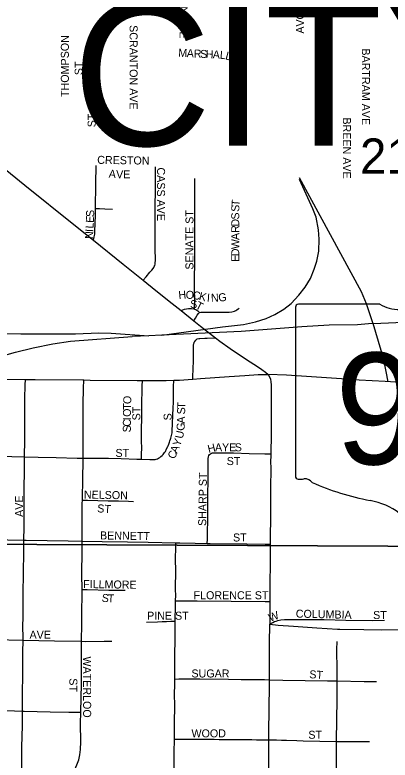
# Model space of a CAD drawing. Extents: x -97 to 34, y -21 to 22.
# Drawn here: x 4.656 to 5.1, y 19.223 to 20.104 of the extents above; entities that cross this region are included whole.
import ezdxf

# ---------------------------------------------------------------- set-up
doc = ezdxf.new("R2010")
doc.units = 0
for name, color, linetype in [('GM_X_City_Street', 7, 'Continuous'), ('GM_X_City_Street_Text', 7, 'Continuous'), ('GM_X_Rail_Line', 7, 'Continuous'), ('GM_X_Section', 7, 'Continuous'), ('GM_X_Section_Text', 7, 'Continuous'), ('GM_X_State_Location', 7, 'Continuous'), ('GM_X_State_Route', 7, 'Continuous'), ('GM_X_State_Shield', 7, 'Continuous'), ('GM_X_Township_Text', 7, 'Continuous')]:
    doc.layers.add(name, color=color, linetype=linetype)

msp = doc.modelspace()

# ---------------------------------------------------------------- linework, layer by layer
at = {"layer": 'GM_X_City_Street'}
for points in [[(4.75175, 19.87547), (4.75216, 19.90473), (4.75252, 19.92642)], [(4.80785, 19.79053), (4.81156, 19.79472), (4.81599, 19.79992), (4.81816, 19.80261), (4.81975, 19.80461), (4.82047, 19.8056), (4.82109, 19.80663), (4.82166, 19.80797), (4.82202, 19.80946), (4.82228, 19.81142), (4.82242, 19.81344), (4.82252, 19.81653), (4.82233, 19.8258), (4.82236, 19.84434), (4.82224, 19.8598), (4.82224, 19.87834), (4.82252, 19.89688), (4.82249, 19.90923), (4.82254, 19.9185), (4.82249, 19.92466)], [(4.86888, 19.75652), (4.86895, 19.75977), (4.86901, 19.76275), (4.86873, 19.7846), (4.86897, 19.81885), (4.86921, 19.91092)], [(4.74904, 19.83794), (4.75013, 19.84192), (4.7507, 19.84511), (4.75097, 19.848), (4.75164, 19.86754), (4.75175, 19.87547)], [(4.75175, 19.87547), (4.75642, 19.87528), (4.76256, 19.87503), (4.77189, 19.87466)], [(4.85305, 19.75462), (4.85708, 19.75622), (4.85912, 19.75672), (4.86179, 19.75704), (4.8654, 19.75717), (4.86794, 19.75685), (4.86888, 19.75652)], [(4.8681, 19.74272), (4.86991, 19.74575), (4.872, 19.74924), (4.87333, 19.75114), (4.87466, 19.75241)], [(4.86888, 19.75652), (4.87029, 19.75603), (4.87257, 19.75451), (4.87466, 19.75241)], [(4.87466, 19.75241), (4.87625, 19.75273), (4.87879, 19.75285), (4.88152, 19.75279), (4.88702, 19.75282), (4.89974, 19.75267), (4.90633, 19.75267), (4.90971, 19.75287), (4.91282, 19.75331), (4.91454, 19.75372), (4.916, 19.75413), (4.91774, 19.75487), (4.91904, 19.75559), (4.92047, 19.75658), (4.92155, 19.75763)], [(4.86665, 19.67348), (4.86676, 19.67633), (4.86747, 19.69511), (4.86757, 19.71082), (4.86755, 19.71237), (4.86771, 19.71394), (4.86797, 19.71557), (4.86823, 19.71661), (4.86849, 19.71745), (4.86897, 19.71819)], [(4.86897, 19.71819), (4.87023, 19.71981), (4.87112, 19.7206), (4.8721, 19.72112), (4.87374, 19.72149), (4.87514, 19.72166), (4.88101, 19.72198), (4.88383, 19.72211), (4.89344, 19.72257)], [(4.6676, 19.58171), (4.6676, 19.58556), (4.66773, 19.59798), (4.66796, 19.62903), (4.66802, 19.65076), (4.66851, 19.66628), (4.66872, 19.67329)], [(4.73686, 19.58003), (4.73682, 19.60364), (4.73687, 19.64398), (4.73738, 19.6626), (4.73764, 19.6726)], [(4.82761, 19.58085), (4.82905, 19.58195), (4.83045, 19.58314), (4.83154, 19.58433), (4.83247, 19.58544), (4.83335, 19.58671), (4.83424, 19.5881), (4.83575, 19.59107), (4.83701, 19.59384), (4.83744, 19.59485), (4.83818, 19.59657), (4.83869, 19.5978), (4.8392, 19.59908), (4.8397, 19.60041), (4.84042, 19.6024), (4.84084, 19.60384), (4.84133, 19.6054), (4.84172, 19.60697), (4.84202, 19.60842), (4.84228, 19.61013), (4.84244, 19.61198), (4.84335, 19.63971), (4.84373, 19.64587), (4.84381, 19.66132), (4.84391, 19.66441), (4.84419, 19.67223)], [(4.80607, 19.57877), (4.80618, 19.58543), (4.80628, 19.59168), (4.80617, 19.60093), (4.80623, 19.6409), (4.80693, 19.66543), (4.80711, 19.67186)], [(4.88568, 19.58341), (4.88669, 19.58457), (4.88777, 19.58534), (4.889, 19.58589), (4.89025, 19.58628), (4.89141, 19.58643), (4.89296, 19.58641), (4.89497, 19.58639), (4.8993, 19.58636), (4.91499, 19.58623), (4.93354, 19.5858), (4.95209, 19.58535), (4.95907, 19.58518)], [(4.59809, 19.58323), (4.60332, 19.58314), (4.61567, 19.58295), (4.63108, 19.58269), (4.65267, 19.58195), (4.6676, 19.58171)], [(4.66685, 19.48317), (4.66695, 19.49861), (4.66731, 19.54209), (4.6676, 19.56693), (4.6676, 19.58171)], [(4.6676, 19.58171), (4.68365, 19.58123), (4.7052, 19.5807), (4.7298, 19.58), (4.73686, 19.58003)], [(4.73603, 19.53043), (4.73644, 19.55718), (4.73687, 19.57574), (4.73686, 19.58003)], [(4.73686, 19.58003), (4.74833, 19.58008), (4.76679, 19.57991), (4.78209, 19.57965), (4.80068, 19.57893), (4.80607, 19.57877)], [(4.80607, 19.57877), (4.81597, 19.57847), (4.81902, 19.57846), (4.82048, 19.5785), (4.82206, 19.57863), (4.82357, 19.5789), (4.82498, 19.57939), (4.82633, 19.58003), (4.82761, 19.58085)], [(4.88386, 19.47935), (4.88395, 19.48447), (4.88446, 19.5149), (4.8845, 19.51807), (4.88455, 19.52113), (4.88451, 19.5303), (4.88461, 19.53317), (4.88461, 19.53603), (4.88469, 19.53905), (4.885, 19.55155), (4.88497, 19.57621), (4.88497, 19.57753), (4.88498, 19.57962), (4.88521, 19.58155), (4.88568, 19.58341)], [(4.73581, 19.48202), (4.73592, 19.5263), (4.73603, 19.53043)], [(4.73603, 19.53043), (4.74212, 19.53029), (4.76658, 19.52979), (4.77863, 19.52945), (4.79047, 19.52923), (4.79664, 19.52883)], [(4.59728, 19.48431), (4.61686, 19.4842), (4.63233, 19.48391), (4.64781, 19.48371), (4.66685, 19.48317)], [(4.6658, 19.36465), (4.66581, 19.37148), (4.66573, 19.37758), (4.6659, 19.39618), (4.66595, 19.40548), (4.6659, 19.4179), (4.66635, 19.44583), (4.66677, 19.46756), (4.66685, 19.48317)], [(4.66685, 19.48317), (4.66949, 19.48309), (4.71912, 19.48227), (4.73581, 19.48202)], [(4.73567, 19.42469), (4.73553, 19.44258), (4.73578, 19.4705), (4.73581, 19.48202)], [(4.73581, 19.48202), (4.75939, 19.48167), (4.78954, 19.48098), (4.81404, 19.48056), (4.8466, 19.48006)], [(4.84643, 19.41134), (4.84655, 19.41812), (4.84634, 19.42433), (4.84637, 19.43367), (4.84658, 19.43883), (4.84648, 19.44299), (4.84645, 19.46471), (4.84652, 19.47093), (4.8466, 19.48006)], [(4.8466, 19.48006), (4.8512, 19.47999), (4.86952, 19.47961), (4.88386, 19.47935)], [(4.88386, 19.47935), (4.88741, 19.47928), (4.93068, 19.47885), (4.95234, 19.47851), (4.95837, 19.47841)], [(4.73507, 19.36351), (4.73523, 19.3843), (4.73536, 19.39647), (4.73569, 19.4209), (4.73567, 19.42469)], [(4.73567, 19.42469), (4.74178, 19.42459), (4.76736, 19.42416), (4.78655, 19.42401)], [(4.84601, 19.38744), (4.84605, 19.39348), (4.84619, 19.3998), (4.8464, 19.40879), (4.84643, 19.41134)], [(4.84643, 19.41134), (4.85087, 19.41145), (4.85994, 19.41149), (4.87178, 19.41145), (4.95226, 19.41074), (4.95803, 19.41068)], [(4.8121, 19.38618), (4.8249, 19.38659), (4.83052, 19.38682), (4.83578, 19.38703), (4.84089, 19.38723), (4.84601, 19.38744)], [(4.84559, 19.31882), (4.84563, 19.32228), (4.84553, 19.33472), (4.84541, 19.34093), (4.84556, 19.34712), (4.84587, 19.36572), (4.84603, 19.37504), (4.84597, 19.38116), (4.84601, 19.38643), (4.84601, 19.38744)], [(4.95737, 19.318), (4.95737, 19.3238), (4.95762, 19.33626), (4.9575, 19.34249), (4.95757, 19.34866), (4.95762, 19.35801), (4.95772, 19.3611), (4.95786, 19.38371)], [(4.95786, 19.38371), (4.96145, 19.38574), (4.96351, 19.38674), (4.96555, 19.38739), (4.96753, 19.38803), (4.97088, 19.38873), (4.97542, 19.3891), (4.99161, 19.38929), (5.01598, 19.38939), (5.02207, 19.38928), (5.04801, 19.3884), (5.07954, 19.38824), (5.09364, 19.38844)], [(4.59598, 19.36586), (4.60664, 19.36575), (4.63147, 19.36554), (4.66562, 19.36466), (4.6658, 19.36465)], [(4.66497, 19.28102), (4.66504, 19.28569), (4.66509, 19.28978), (4.66516, 19.2945), (4.66521, 19.29833), (4.66529, 19.30363), (4.66535, 19.30957), (4.66541, 19.31602), (4.66545, 19.32107), (4.66549, 19.32503), (4.66553, 19.32912), (4.66557, 19.33307), (4.66561, 19.3378), (4.66565, 19.34266), (4.66569, 19.34661), (4.66575, 19.35297), (4.6658, 19.36222), (4.6658, 19.36465)], [(4.6658, 19.36465), (4.70287, 19.36401), (4.73507, 19.36351)], [(4.73507, 19.36351), (4.74006, 19.36343), (4.76165, 19.36375), (4.77095, 19.36365)], [(4.73416, 19.27957), (4.735, 19.31317), (4.73499, 19.35341), (4.73507, 19.36351)], [(5.0375, 19.31656), (5.03749, 19.32919), (5.03738, 19.35387), (5.0376, 19.36316)], [(4.84506, 19.24776), (4.8452, 19.25389), (4.84517, 19.26636), (4.84547, 19.28813), (4.84516, 19.30053), (4.84551, 19.31293), (4.84559, 19.31882)], [(4.84559, 19.31882), (4.85024, 19.31894), (4.85955, 19.31919), (4.87507, 19.31894), (4.90917, 19.31862), (4.92417, 19.31847), (4.95167, 19.31814), (4.95737, 19.318)], [(4.95686, 19.24688), (4.95688, 19.25243), (4.95712, 19.2866), (4.95745, 19.30827), (4.9574, 19.31449), (4.95737, 19.318)], [(4.95737, 19.318), (4.97339, 19.31761), (5.02619, 19.31673), (5.0375, 19.31656)], [(5.03686, 19.24518), (5.03687, 19.2459), (5.03756, 19.29519), (5.0375, 19.31656)], [(5.0375, 19.31656), (5.06953, 19.31609), (5.08406, 19.31584)], [(4.59643, 19.28289), (4.63586, 19.28191), (4.66497, 19.28102)], [(4.6685, 19.13409), (4.66685, 19.13448), (4.66608, 19.13479), (4.66522, 19.1354), (4.66442, 19.13657), (4.66406, 19.13819), (4.66391, 19.13982), (4.66386, 19.14266), (4.66389, 19.15508), (4.66381, 19.1581), (4.66384, 19.16112), (4.66375, 19.1672), (4.66384, 19.17647), (4.66417, 19.19819), (4.66448, 19.21991), (4.66448, 19.23853), (4.66504, 19.26334), (4.66513, 19.27265), (4.66497, 19.28102)], [(4.66497, 19.28102), (4.66696, 19.28095), (4.69807, 19.28008), (4.71986, 19.27966), (4.72479, 19.27969), (4.73416, 19.27957)], [(4.6685, 19.13409), (4.67125, 19.13545), (4.67382, 19.13713), (4.67865, 19.14095), (4.68309, 19.14521), (4.68927, 19.15208), (4.6968, 19.16186), (4.70384, 19.17197), (4.71204, 19.18501), (4.72135, 19.201), (4.72711, 19.2119), (4.72967, 19.2175), (4.73166, 19.22332), (4.73305, 19.22932), (4.73387, 19.23543), (4.73423, 19.24466), (4.73398, 19.26622), (4.73416, 19.27957)], [(4.84457, 19.1783), (4.84487, 19.20417), (4.84469, 19.23216), (4.84506, 19.24776)], [(4.84506, 19.24776), (4.84656, 19.24776), (4.84899, 19.24775), (4.85269, 19.24775), (4.8573, 19.24775), (4.86081, 19.24775), (4.86503, 19.24774), (4.87049, 19.24773), (4.8731, 19.24772), (4.87847, 19.24769), (4.88116, 19.24767), (4.88849, 19.24762), (4.89186, 19.24756), (4.89806, 19.24754), (4.91344, 19.24745), (4.91943, 19.24744), (4.92511, 19.24748), (4.92803, 19.24745), (4.93663, 19.24723), (4.94228, 19.24713), (4.951, 19.247), (4.95686, 19.24688)], [(4.95659, 19.17674), (4.9566, 19.17869), (4.95657, 19.19079), (4.9568, 19.197), (4.95673, 19.1998), (4.95684, 19.22765), (4.95686, 19.24688)], [(4.95686, 19.24688), (4.96275, 19.2468), (4.96564, 19.24679), (4.97164, 19.24657), (4.97774, 19.24645), (4.99, 19.24611), (4.99747, 19.24596), (5.03686, 19.24518)], [(5.03616, 19.17586), (5.03632, 19.19676), (5.03674, 19.22449), (5.03686, 19.24518)], [(5.03686, 19.24518), (5.04217, 19.24505), (5.06351, 19.24485), (5.07581, 19.24507)]]:
    msp.add_lwpolyline(points, dxfattribs=at)
at = {"layer": 'GM_X_Rail_Line'}
for points in [[(5.07985, 19.74006), (5.07224, 19.76264), (5.06653, 19.77664), (4.993, 19.9115)], [(4.82995, 19.72561), (4.90186, 19.73546), (4.9267, 19.73839), (4.94107, 19.74143), (4.95339, 19.74544), (4.96376, 19.75003), (4.97432, 19.75649), (4.98312, 19.76314), (4.99232, 19.77272), (4.99965, 19.7823), (5.00591, 19.79277), (5.01051, 19.80353), (5.01354, 19.81291), (5.01579, 19.82484), (5.01628, 19.83932), (5.0154, 19.85008), (5.01266, 19.86504), (5.00875, 19.87501), (4.99299, 19.90954)], [(3.55146, 19.84605), (3.99437, 19.79548), (4.36844, 19.75302), (4.56422, 19.73118), (4.58914, 19.72923), (4.61241, 19.7276), (4.66323, 19.72698), (4.72805, 19.72735), (4.75546, 19.72823), (4.77023, 19.72786), (4.81467, 19.72488)], [(5.07455, 19.73891), (5.0615, 19.738), (5.02805, 19.73723), (4.99596, 19.73538), (4.9239, 19.73003), (4.82995, 19.72561)], [(5.08011, 19.73929), (5.07455, 19.73891)], [(5.08011, 19.73929), (5.07985, 19.74006)], [(5.08011, 19.73929), (5.12506, 19.74133)], [(5.09818, 19.67056), (5.09279, 19.69666), (5.08011, 19.73929)], [(4.82995, 19.72561), (4.81467, 19.72488)], [(4.63887, 19.70027), (4.65686, 19.70533), (4.67777, 19.71068), (4.7012, 19.71525), (4.72192, 19.71846), (4.79498, 19.72393)], [(4.81467, 19.72488), (4.79498, 19.72393)]]:
    msp.add_lwpolyline(points, dxfattribs=at)
at = {"layer": 'GM_X_Section'}
for points in [[(4.59907, 20.48403), (5.59805, 20.47457), (5.59615, 19.47364), (4.59865, 19.47855)], [(4.59865, 19.47855), (5.59615, 19.47364), (5.59082, 18.47236), (4.59557, 18.47233)]]:
    msp.add_lwpolyline(points, close=True, dxfattribs=at)
at = {"layer": 'GM_X_State_Route'}
for points in [[(4.60122, 19.95654), (4.62915, 19.93424), (4.66788, 19.90309), (4.72606, 19.85642), (4.74904, 19.83794), (4.78415, 19.80968), (4.80785, 19.79053), (4.82281, 19.77844), (4.84237, 19.76308), (4.85305, 19.75462), (4.8681, 19.74272), (4.87591, 19.73633), (4.88286, 19.73083), (4.89017, 19.72505), (4.89344, 19.72257), (4.89873, 19.71857), (4.91115, 19.70981), (4.93154, 19.69606), (4.94212, 19.68913), (4.94841, 19.68504), (4.95266, 19.68192), (4.95603, 19.67899)], [(4.54599, 19.67245), (4.55588, 19.67222), (4.5776, 19.673), (4.58596, 19.67309), (4.59001, 19.67314), (4.59856, 19.67326), (4.61174, 19.67342), (4.66872, 19.67329), (4.68006, 19.67326), (4.73665, 19.67261)], [(4.73665, 19.67261), (4.73764, 19.6726), (4.74527, 19.67251), (4.80104, 19.67188), (4.80711, 19.67186), (4.816, 19.67183), (4.83538, 19.67186), (4.84419, 19.67223), (4.85093, 19.67252), (4.86128, 19.67302), (4.86665, 19.67348), (4.87573, 19.67426), (4.9098, 19.67661), (4.92839, 19.67807), (4.94399, 19.67922), (4.95603, 19.67899)], [(4.95603, 19.67899), (4.95749, 19.67631), (4.95856, 19.67358), (4.95914, 19.67051), (4.95941, 19.66666), (4.9594, 19.65975), (4.95939, 19.64811), (4.95932, 19.60786), (4.95908, 19.58615), (4.95907, 19.58518), (4.9589, 19.57373), (4.95895, 19.57071), (4.95893, 19.5627), (4.95891, 19.55033), (4.9589, 19.54131), (4.95888, 19.53368), (4.95866, 19.51822), (4.95837, 19.47841), (4.95827, 19.46541), (4.95808, 19.42209), (4.95803, 19.41068), (4.95801, 19.40654), (4.95786, 19.38371)], [(5.05471, 19.67312), (4.97754, 19.67823), (4.95603, 19.67899)], [(5.1646, 19.66835), (5.16362, 19.66839), (5.1593, 19.66856), (5.15293, 19.66855), (5.14899, 19.66833), (5.14545, 19.668), (5.1377, 19.66842), (5.1188, 19.66943), (5.11296, 19.66961), (5.09448, 19.6706), (5.06369, 19.67252), (5.05471, 19.67312)], [(4.95786, 19.38371), (4.9678, 19.38269), (4.9858, 19.38134), (5.01352, 19.37928), (5.03817, 19.37801), (5.04062, 19.37796)], [(5.04062, 19.37796), (5.06904, 19.3773), (5.09068, 19.37715), (5.11233, 19.37738), (5.13397, 19.37788), (5.15248, 19.3787), (5.15604, 19.37875), (5.17049, 19.37984)]]:
    msp.add_lwpolyline(points, dxfattribs=at)
at = {"layer": 'GM_X_State_Shield'}
for p, q in [((5.0882, 19.76232), (4.99168, 19.76232)), ((4.98843, 19.75887), (4.98843, 19.55875))]:
    msp.add_line(p, q, dxfattribs=at)
for centre, major_axis, start_param, end_param in [((4.99221, 19.7593), (0.00382, 0), 1.712693, 3.28349), ((5.11118, 19.78555), (0.03703, 0), 4.042523, 4.731795), ((4.99224, 19.55831), (0.00385, 0), 3.00124, 4.508301), ((4.99283, 19.57879), (0.0294, 0), 4.665946, 4.897461), ((4.99884, 19.54721), (0.0106, 0), 0.519207, 1.627899), ((5.13266, 19.72701), (0.2524, 0), 4.195997, 4.488961), ((5.05741, 19.46885), (0.07897, 0), 0.823519, 1.323587)]:
    msp.add_ellipse(centre, major_axis=major_axis, ratio=0.8, start_param=start_param, end_param=end_param, dxfattribs=at)

# ---------------------------------------------------------------- texts
at = {"layer": 'GM_X_City_Street_Text'}
for s, height, rotation, p in [('MILBURN AVE', 0.0094697, 270, (4.85111, 20.16228)), ('O', 0.00947, 89.99284, (4.99839, 20.09894)), ('V', 0.00947, 89.97813, (4.99838, 20.09061)), ('SCRANTON AVE', 0.0094697, 270, (4.79194, 20.09228)), ('A', 0.00947, 89.97813, (4.99838, 20.08228)), ('THOMPSON', 0.00947, 90, (4.72004, 20.00728)), ('M', 0.00947, 357.33954, (4.8494, 20.05489)), ('A', 0.00947, 357.33294, (4.85939, 20.05443)), ('R', 0.00947, 357.32797, (4.86772, 20.05404)), ('S', 0.00947, 357.32177, (4.87521, 20.05369)), ('H', 0.00947, 357.33572, (4.88187, 20.05338)), ('A', 0.00947, 357.33294, (4.8902, 20.05299)), ('L', 0.00947, 354.41719, (4.89839, 20.05261)), ('L', 0.00947, 345.47338, (4.90464, 20.05203)), ('BARTRAM AVE', 0.0094697, 270, (5.06694, 20.06478)), ('S', 0.00947, 342.77474, (4.91338, 20.04967)), ('T', 0.00947, 342.74865, (4.91974, 20.04769)), ('ST', 0.00947, 90, (4.73634, 20.03311)), ('ST', 0.00947, 90, (4.75171, 19.97144)), ('BREEN AVE', 0.00947, 270, (5.04444, 19.98311)), ('CRESTON', 0.00947, 359.10386, (4.75354, 19.92822)), ('A', 0.00947, 355.25088, (4.76696, 19.91202)), ('V', 0.00947, 358.75423, (4.7759, 19.91129)), ('E', 0.00947, 359.92078, (4.78444, 19.91111)), ('CASS AVE', 0.00947, 270, (4.82444, 19.92394)), ('T', 0.00947, 85.48815, (4.92192, 19.87791)), ('S', 0.00947, 88.36029, (4.92173, 19.87137)), ('E', 0.00947, 86.79684, (4.7495, 19.8582)), ('S', 0.00947, 88.91457, (4.74988, 19.86524)), ('SENATE ST', 0.00947, 90, (4.86755, 19.80311)), ('S', 0.00947, 90, (4.92173, 19.86228)), ('L', 0.00947, 86.64462, (4.74911, 19.85153)), ('D', 0.00947, 89.98125, (4.92173, 19.85394)), ('I', 0.00947, 86.64421, (4.74887, 19.84737)), ('R', 0.00947, 89.9757, (4.92172, 19.84644)), ('N', 0.00947, 86.65407, (4.74838, 19.83905)), ('A', 0.00947, 89.97813, (4.92172, 19.83811)), ('W', 0.00947, 89.98318, (4.92172, 19.82728)), ('D', 0.00947, 89.98125, (4.92171, 19.81894)), ('E', 0.00947, 89.97267, (4.92171, 19.81228)), ('H', 0.00947, 5.09944, (4.85013, 19.76822)), ('O', 0.00947, 355.29625, (4.85801, 19.76896)), ('C', 0.00947, 353.60082, (4.86624, 19.76828)), ('K', 0.00947, 346.40905, (4.87338, 19.7675)), ('I', 0.00947, 356.02956, (4.8832, 19.76528)), ('N', 0.00947, 1.50299, (4.88834, 19.76497)), ('G', 0.00947, 5.48292, (4.89739, 19.76523)), ('S', 0.00947, 357.07482, (4.86337, 19.75777)), ('T', 0.00947, 332.66519, (4.869, 19.75771)), ('O', 0.00947, 86.39093, (4.79362, 19.64379)), ('T', 0.00947, 88.72654, (4.85775, 19.63844)), ('O', 0.00947, 89.57614, (4.79352, 19.62893)), ('T', 0.00947, 89.58089, (4.79358, 19.63726)), ('ST', 0.00947, 90, (4.80467, 19.62478)), ('S', 0.00947, 88.71603, (4.85761, 19.63178)), ('S', 0.00947, 90, (4.84171, 19.62478)), ('A', 0.00947, 88.56277, (4.85734, 19.62091)), ('C', 0.00947, 89.56281, (4.79343, 19.61726)), ('I', 0.00947, 89.56296, (4.79348, 19.62476)), ('G', 0.00947, 86.63738, (4.85684, 19.61225)), ('S', 0.00947, 89.59016, (4.79338, 19.61059)), ('U', 0.00947, 77.74136, (4.85486, 19.60251)), ('Y', 0.00947, 69.27153, (4.85147, 19.59325)), ('A', 0.00947, 67.32, (4.84813, 19.58524)), ('H', 0.00947, 13.25178, (4.88548, 19.58617)), ('A', 0.00947, 1.46432, (4.89309, 19.58802)), ('Y', 0.00947, 0.00001, (4.90136, 19.58823)), ('E', 0.00947, 0.00001, (4.90969, 19.58823)), ('S', 0.00947, 0.00001, (4.91635, 19.58823)), ('ST', 0.00947, 0.00001, (4.77516, 19.58156)), ('C', 0.00947, 67.07564, (4.84519, 19.57829)), ('ST', 0.00947, 0.00001, (4.90683, 19.57194)), ('SHARP ST', 0.00947, 89.13129, (4.88255, 19.49981)), ('NELSON', 0.00947, 358.96018, (4.73774, 19.53239)), ('AVE', 0.00947, 90, (4.66588, 19.51061)), ('ST', 0.00947, 356.18786, (4.75336, 19.51614)), ('BENNETT', 0.00947, 359.08765, (4.75686, 19.48406)), ('ST', 0.00947, 0.00001, (4.91433, 19.48156)), ('FILLMORE', 0.00947, 359.15624, (4.73691, 19.42656)), ('S', 0.00947, 354.44439, (4.75859, 19.41036)), ('T', 0.00947, 358.02171, (4.76587, 19.40967)), ('FLORENCE ST', 0.0094697, 0.00001, (4.86766, 19.41323)), ('W', 0.00947, 21.19565, (4.95855, 19.38638)), ('COLUMBIA', 0.00947, 358.6793, (4.98855, 19.39157)), ('ST', 0.00947, 0.00001, (5.08016, 19.3899)), ('PINE ST', 0.00947, 0.00001, (4.81266, 19.38906)), ('AVE', 0.00947, 0.00001, (4.67349, 19.36656)), ('WATERLOO', 0.00947, 270, (4.73694, 19.34561)), ('SUGAR', 0.00947, 0.00001, (4.86516, 19.32073)), ('ST', 0.00947, 356.42622, (5.00444, 19.31989)), ('ST', 0.00947, 270, (4.72065, 19.31978)), ('WOOD', 0.00947, 0.00001, (4.86516, 19.24989)), ('ST', 0.00947, 0.00001, (5.00349, 19.24823))]:
    msp.add_text(s, height=height, rotation=rotation, dxfattribs=at).set_placement(p)
at = {"layer": 'GM_X_Section_Text'}
msp.add_text('21', height=0.041856, rotation=0.00001, dxfattribs=at).set_placement((5.06474, 19.9164))
at = {"layer": 'GM_X_State_Location'}
msp.add_text('95D', height=0.000189, rotation=0.00001, dxfattribs=at).set_placement((5.07683, 19.63173))
at = {"layer": 'GM_X_State_Shield'}
msp.add_text('95D', height=0.131836, dxfattribs=at).set_placement((5.03517, 19.57286))
at = {"layer": 'GM_X_Township_Text'}
msp.add_text('CITY OF MARION', height=0.1704545, rotation=0.00001, dxfattribs=at).set_placement((4.72404, 19.9498))

doc.saveas('drawing.dxf')
